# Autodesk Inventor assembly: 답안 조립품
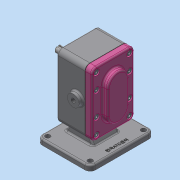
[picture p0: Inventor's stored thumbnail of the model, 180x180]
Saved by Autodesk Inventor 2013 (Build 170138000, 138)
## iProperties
Created: 2020-04
Part Number: 답안 조립품
Document SubType Name: Assembly
Designer: dgall
Author: dgall
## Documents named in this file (11)
- C:\Users\dgall\Desktop\700407V1019\답안 조립품.iam
- C:\Users\dgall\Desktop\700407V1019\본체.ipt
- C:\Users\dgall\Desktop\700407V1019\메인축.ipt
- C:\Users\dgall\Desktop\700407V1019\스퍼기어.ipt
- C:\Users\dgall\Desktop\700407V1019\키 6 x 6 x 18.ipt
- C:\Users\dgall\Desktop\700407V1019\베어링부시.ipt
- C:\Users\dgall\Desktop\700407V1019\오일 실 16 28 7.ipt
- C:\Users\dgall\Desktop\700407V1019\서브축.ipt
- C:\Users\dgall\Desktop\700407V1019\커버.ipt
- C:\Users\dgall\Desktop\700407V1019\개스킷.ipt
- C:\Users\dgall\Desktop\700407V1019\볼트 M5.ipt
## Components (1 placed, 1 different names)
1. 개스킷:1
## Component patterns: 구성요소 패턴 5:2 (2 elements)
